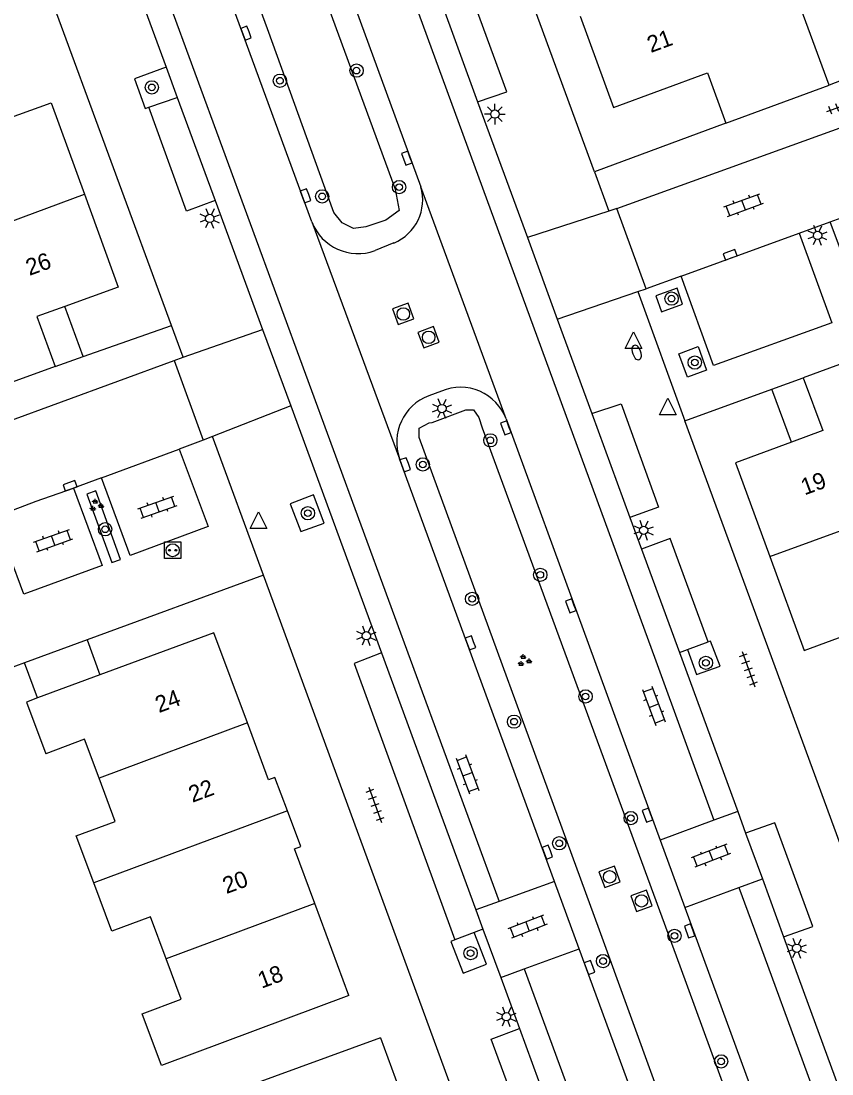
# Model space of a CAD drawing. Extents: x 128000 to 131008, y 398996 to 402500.
# Drawn here: x 128334.1 to 128382.8, y 399087 to 399150.2 of the extents above; entities that cross this region are included whole.
import ezdxf

# ---------------------------------------------------------------- set-up
doc = ezdxf.new("R2010")
doc.units = 0
for name, color, linetype in [('gg-afsc-erfafscheiding', 7, 'Continuous'), ('gg-anno-huisnummerreeks BGT', 7, 'Continuous'), ('gg-bbg-gedigitaliseerde bebouwing', 7, 'Continuous'), ('gg-bbg-hoofdgebouw', 7, 'Continuous'), ('gg-bbg-luifel en loopbrug', 7, 'Continuous'), ('gg-bbg-tussenscheiding', 7, 'Continuous'), ('gg-knt-verharding', 7, 'Continuous'), ('gg-knt-verharding nz', 7, 'Continuous'), ('gt-grn-groengrens NZ', 7, 'Continuous'), ('gt-grn-weggrens', 7, 'Continuous'), ('gt-symb-boom', 7, 'Continuous'), ('gt-symb-brandkraan', 7, 'Continuous'), ('gt-symb-groenvak', 7, 'Continuous'), ('gt-symb-klinker verharding', 7, 'Continuous'), ('gt-symb-kolk', 7, 'Continuous'), ('gt-symb-laadpunt elektrisch vervoer', 7, 'Continuous'), ('gt-symb-lichtmast', 7, 'Continuous'), ('gt-symb-rioolschacht', 7, 'Continuous'), ('gt-symb-tegel verharding', 7, 'Continuous'), ('gt-symb-waterafsluiter', 7, 'Continuous')]:
    doc.layers.add(name, color=color, linetype=linetype)

# ---------------------------------------------------------------- blocks, each defined once
blk = doc.blocks.new('gt0-KOLK')
at = {"layer": 'gt-symb-kolk'}
blk.add_lwpolyline([(0, 0), (0.375, 0), (0.375, 0.4), (-0.375, 0.4), (-0.375, 0), (0, 0)], dxfattribs=at)
blk = doc.blocks.new('gt0-KL1')
at = {"layer": 'gt-symb-klinker verharding'}
for p, q in [((-1.15, 0.3), (1.15, 0.3)), ((-1, -0.3), (-1, 0.3)), ((-0.5, 0.3), (-0.5, 0.45)), ((0, -0.3), (0, 0.3)), ((0.5, 0.3), (0.5, 0.45)), ((1, -0.3), (1, 0.3)), ((-1.15, -0.3), (1.15, -0.3)), ((-0.5, -0.45), (-0.5, -0.3)), ((0.5, -0.45), (0.5, -0.3))]:
    blk.add_line(p, q, dxfattribs=at)
blk = doc.blocks.new('gt0-TEG1')
at = {"layer": 'gt-symb-tegel verharding'}
for p, q in [((-1.125, 0), (1.125, 0)), ((-0.9, -0.25), (-0.9, 0.25)), ((-0.45, -0.25), (-0.45, 0.25)), ((0, -0.25), (0, 0.25)), ((0.45, -0.25), (0.45, 0.25)), ((0.9, -0.25), (0.9, 0.25))]:
    blk.add_line(p, q, dxfattribs=at)
blk = doc.blocks.new('gt0-BOOM')
at = {"layer": 'gt-symb-boom'}
for radius in [0.4, 0.2]:
    blk.add_circle((0, 0), radius, dxfattribs=at)
blk = doc.blocks.new('gt0-RS')
at = {"layer": 'gt-symb-rioolschacht'}
blk.add_lwpolyline([(-0.5, -0.5), (0.5, -0.5), (0.5, 0.5), (-0.5, 0.5)], close=True, dxfattribs=at)
blk.add_circle((0, 0), 0.375, dxfattribs=at)
blk = doc.blocks.new('gt0-LMAST')
at = {"layer": 'gt-symb-lichtmast'}
for p, q in [((-0.182, 0.173), (-0.447, 0.438)), ((-0.005, 0.246), (-0.005, 0.621)), ((0.172, 0.173), (0.437, 0.438)), ((-0.255, -0.004), (-0.63, -0.004)), ((-0.182, -0.181), (-0.447, -0.446)), ((-0.005, -0.254), (-0.005, -0.629)), ((0.437, -0.446), (0.172, -0.181)), ((0.245, -0.004), (0.62, -0.004))]:
    blk.add_line(p, q, dxfattribs=at)
blk.add_circle((-0.005, -0.004), 0.25, dxfattribs=at)
blk = doc.blocks.new('gt0-WAFSL')
at = {"layer": 'gt-symb-waterafsluiter'}
for p, q in [((-0.5, -0.333), (0, 0.667)), ((0, 0.667), (0.5, -0.333)), ((0.5, -0.333), (-0.5, -0.333))]:
    blk.add_line(p, q, dxfattribs=at)
blk = doc.blocks.new('gt0-BR')
at = {"layer": 'gt-symb-brandkraan'}
for centre, radius, start, end in [((-0.244, 0), 0.206, 107.56694, 252.43307), ((0.599, -2.664), 3, 106.89205, 107.56694), ((0, -0.691), 0.938, 73.10799, 106.89205), ((-0.599, -2.664), 3, 72.43309, 73.10799), ((0.244, 0), 0.206, 287.56695, 72.43309), ((0.599, 2.664), 3, 252.43307, 253.10797), ((0, 0.691), 0.938, 253.10797, 286.89206), ((-0.599, 2.664), 3, 286.89206, 287.56695)]:
    blk.add_arc(centre, radius, start, end, dxfattribs=at)
blk = doc.blocks.new('gt0-GRVAK')
at = {"layer": 'gt-symb-groenvak'}
for p, q in [((-0.11, 0.189), (-0.228, 0.24)), ((-0.182, 0.153), (0.088, 0.153)), ((-0.091, 0.211), (-0.156, 0.322)), ((-0.047, 0.214), (-0.047, 0.393)), ((-0.004, 0.211), (0.061, 0.322)), ((0.015, 0.189), (0.133, 0.24)), ((0.262, -0.052), (0.197, 0.059)), ((0.305, -0.049), (0.305, 0.13)), ((0.349, -0.052), (0.414, 0.059)), ((-0.245, -0.228), (-0.363, -0.177)), ((-0.318, -0.264), (-0.047, -0.264)), ((-0.226, -0.206), (-0.291, -0.095)), ((-0.183, -0.203), (-0.183, -0.024)), ((-0.139, -0.206), (-0.074, -0.095)), ((-0.12, -0.228), (-0.002, -0.177)), ((0.243, -0.074), (0.125, -0.023)), ((0.17, -0.11), (0.441, -0.11)), ((0.368, -0.074), (0.486, -0.023))]:
    blk.add_line(p, q, dxfattribs=at)
blk = doc.blocks.new('gt0-LEV')
at = {"layer": 'gt-symb-laadpunt elektrisch vervoer'}
blk.add_lwpolyline([(-0.486, 0.501), (0.486, 0.501), (0.486, -0.499), (-0.486, -0.499)], close=True, dxfattribs=at)
for centre, radius in [((0, 0), 0.393), ((-0.186, 0), 0.0566), ((0.186, 0), 0.0566)]:
    blk.add_circle(centre, radius, dxfattribs=at)

msp = doc.modelspace()

# ---------------------------------------------------------------- linework, layer by layer
at = {"layer": 'gg-afsc-erfafscheiding'}
for p, q in [((128387.99, 399148.45), (128382.63, 399146.39)), ((128334.296, 399111.668), (128322.793, 399107.451))]:
    msp.add_line(p, q, dxfattribs=at)
at = {"layer": 'gg-bbg-gedigitaliseerde bebouwing'}
for points in [[(128338.762, 399104.727), (128337.89, 399107.069), (128335.56, 399106.2)], [(128338.448, 399098.435), (128337.395, 399101.264), (128339.728, 399102.132), (128338.762, 399104.727)], [(128342.8, 399093.881), (128341.862, 399096.4), (128339.53, 399095.531), (128338.448, 399098.435)], [(128353.78, 399091.66), (128342.51, 399087.469), (128341.356, 399090.569), (128343.707, 399091.445), (128342.8, 399093.881)], [(128355.67, 399089.13), (128344.412, 399085.014), (128345.544, 399081.92), (128347.889, 399082.777), (128348.759, 399080.399)]]:
    msp.add_lwpolyline(points, dxfattribs=at)
at = {"layer": 'gg-bbg-hoofdgebouw'}
for p, q in [((128376.42, 399144.11), (128382.63, 399146.39)), ((128390.95, 399132.41), (128381.07, 399128.8)), ((128336.12, 399129.48), (128327.001, 399126.173)), ((128338.817, 399110.942), (128335.064, 399109.555)), ((128353.78, 399091.66), (128351.719, 399097.202)), ((128355.67, 399089.13), (128357.67, 399083.658))]:
    msp.add_line(p, q, dxfattribs=at)
for points in [[(128382.63, 399146.39), (128380.52, 399152.12), (128378.08, 399151.22), (128377.065, 399153.986)], [(128367.664, 399150.54), (128369.68, 399145.05), (128375.32, 399147.12), (128376.42, 399144.11)], [(128332.702, 399144.175), (128335.88, 399145.33), (128337.881, 399139.829)], [(128337.881, 399139.829), (128339.91, 399134.25), (128336.708, 399133.089)], [(128336.708, 399133.089), (128335.03, 399132.48), (128336.12, 399129.48)], [(128381.07, 399128.8), (128382.24, 399125.63), (128380.366, 399124.932)], [(128380.366, 399124.932), (128377, 399123.68), (128379.064, 399118.047)], [(128379.064, 399118.047), (128381.13, 399112.41), (128384.493, 399113.649)], [(128347.68, 399108.048), (128345.66, 399113.47), (128338.817, 399110.942)], [(128335.064, 399109.555), (128334.4, 399109.31), (128335.56, 399106.2)], [(128350.08, 399102.766), (128349.33, 399104.78), (128348.95, 399104.64), (128347.68, 399108.048)], [(128351.719, 399097.202), (128350.5, 399100.48), (128350.88, 399100.62), (128350.08, 399102.766)]]:
    msp.add_lwpolyline(points, dxfattribs=at)
at = {"layer": 'gg-bbg-luifel en loopbrug'}
for p, q in [((128337.818, 399130.077), (128336.708, 399133.089)), ((128336.12, 399129.48), (128337.818, 399130.077)), ((128379.182, 399128.113), (128381.07, 399128.8)), ((128380.366, 399124.932), (128379.182, 399128.113)), ((128338.052, 399113.045), (128334.296, 399111.668)), ((128338.052, 399113.045), (128338.817, 399110.942)), ((128335.064, 399109.555), (128334.296, 399111.668))]:
    msp.add_line(p, q, dxfattribs=at)
at = {"layer": 'gg-bbg-tussenscheiding'}
for p, q in [((128329.843, 399136.835), (128337.881, 399139.829)), ((128379.064, 399118.047), (128390.334, 399122.193)), ((128347.68, 399108.048), (128338.762, 399104.727)), ((128350.08, 399102.766), (128338.448, 399098.435)), ((128351.719, 399097.202), (128342.8, 399093.881))]:
    msp.add_line(p, q, dxfattribs=at)
at = {"layer": 'gg-knt-verharding'}
for p, q in [((128368.53, 399141.17), (128349.82, 399192.151)), ((128343.12, 399131.94), (128324.56, 399182.36)), ((128349.985, 399162.408), (128358.097, 399140.276)), ((128351.554, 399138.165), (128343.596, 399159.823)), ((128339.739, 399155.796), (128342.797, 399147.471)), ((128342.797, 399147.471), (128343.466, 399145.649)), ((128369.87, 399138.98), (128392.622, 399147.204)), ((128341.765, 399145.061), (128343.466, 399145.649)), ((128361.506, 399145.394), (128364.496, 399137.232)), ((128376.42, 399144.11), (128368.53, 399141.17)), ((128345.743, 399139.452), (128348.588, 399131.706)), ((128371.63, 399134.15), (128369.87, 399138.98)), ((128380.83, 399137.492), (128382.694, 399138.17)), ((128364.496, 399137.232), (128366.293, 399132.326)), ((128356.48, 399136.9), (128355.349, 399136.45)), ((128373.734, 399134.914), (128371.63, 399134.15)), ((128366.293, 399132.326), (128368.373, 399126.648)), ((128337.818, 399130.077), (128343.12, 399131.94)), ((128348.588, 399131.706), (128350.277, 399127.108)), ((128343.272, 399129.838), (128345.027, 399125.049)), ((128359.34, 399128.001), (128358.57, 399127.72)), ((128373.95, 399126.21), (128379.182, 399128.113)), ((128350.277, 399127.108), (128355.727, 399112.271)), ((128363.22, 399126.33), (128372.471, 399101.015)), ((128405.733, 399039.553), (128373.95, 399126.21)), ((128345.027, 399125.049), (128343.575, 399124.508)), ((128366.131, 399098.53), (128356.823, 399123.932)), ((128338.912, 399122.783), (128337.221, 399122.164)), ((128370.661, 399120.4), (128371.356, 399118.503)), ((128348.65, 399116.93), (128338.052, 399113.045)), ((128367.65, 399065.05), (128348.65, 399116.93)), ((128374.11, 399112.468), (128375.357, 399112.917)), ((128373.63, 399112.295), (128374.11, 399112.468)), ((128373.63, 399112.295), (128377.134, 399102.73)), ((128377.134, 399102.73), (128375.692, 399102.2)), ((128377.134, 399102.73), (128377.609, 399101.433)), ((128375.692, 399102.2), (128372.471, 399101.015)), ((128372.471, 399101.015), (128373.955, 399096.954)), ((128377.195, 399098.162), (128378.613, 399098.691)), ((128366.131, 399098.53), (128362.81, 399097.328)), ((128367.615, 399094.48), (128366.131, 399098.53)), ((128373.955, 399096.954), (128377.195, 399098.162)), ((128362.81, 399097.328), (128361.402, 399096.819)), ((128373.955, 399096.954), (128382.45, 399073.709)), ((128361.298, 399095.459), (128360.143, 399095.009)), ((128361.826, 399095.665), (128361.298, 399095.459)), ((128361.826, 399095.665), (128362.894, 399092.756)), ((128379.89, 399095.204), (128383.914, 399084.219)), ((128364.3, 399093.269), (128367.615, 399094.48)), ((128376.08, 399071.38), (128367.615, 399094.48)), ((128362.894, 399092.756), (128364.3, 399093.269)), ((128362.894, 399092.756), (128364.021, 399089.688))]:
    msp.add_line(p, q, dxfattribs=at)
for points in [[(128361.506, 399145.394), (128363.263, 399145.978), (128359.248, 399156.921)], [(128342.797, 399147.471), (128340.894, 399146.772), (128341.527, 399144.979), (128341.765, 399145.061)], [(128345.743, 399139.452), (128344.026, 399138.818), (128341.765, 399145.061)], [(128389.754, 399140.734), (128391.714, 399135.405), (128384.681, 399132.818), (128382.694, 399138.17)], [(128380.83, 399137.492), (128382.783, 399132.104), (128375.685, 399129.535), (128373.734, 399134.914)], [(128372.547, 399132.77), (128373.82, 399133.219), (128373.493, 399134.191), (128372.222, 399133.729), (128372.547, 399132.77)], [(128373.595, 399130.246), (128374.747, 399130.688), (128375.263, 399129.264), (128374.118, 399128.838), (128373.595, 399130.246)], [(128295.703, 399112.316), (128333.127, 399126.116), (128343.272, 399129.838)], [(128368.373, 399126.648), (128370.122, 399127.234), (128372.376, 399121.014), (128370.661, 399120.4)], [(128343.575, 399124.508), (128345.325, 399119.858), (128340.633, 399118.126), (128338.912, 399122.783)], [(128337.221, 399122.164), (128338.957, 399117.507), (128334.255, 399115.794), (128332.512, 399120.442)], [(128339.542, 399117.698), (128340.058, 399117.884), (128338.577, 399122), (128338.039, 399121.803), (128339.542, 399117.698)], [(128350.893, 399119.563), (128352.298, 399120.063), (128351.655, 399121.759), (128350.252, 399121.227), (128350.893, 399119.563)], [(128375.357, 399112.917), (128373.072, 399119.145), (128371.356, 399118.503)], [(128374.11, 399112.468), (128374.655, 399110.955), (128376.068, 399111.472), (128375.507, 399112.971), (128375.357, 399112.917)], [(128355.727, 399112.271), (128354.087, 399111.63), (128360.143, 399095.009)], [(128379.89, 399095.204), (128381.644, 399095.816), (128379.364, 399102.055), (128377.609, 399101.433)], [(128360.143, 399095.009), (128359.9, 399094.914), (128360.641, 399093.013), (128362.039, 399093.558), (128361.298, 399095.459)], [(128366.338, 399078.12), (128362.33, 399089.049), (128364.021, 399089.688)]]:
    msp.add_lwpolyline(points, dxfattribs=at)
for centre, radius, start, end in [((128355.394, 399139.495), 2.813, 292.69937, 16.11466), ((128354.318, 399139.225), 2.961, 200.98712, 290.37547), ((128359.634, 399124.933), 2.984, 110.8884, 199.59393), ((128360.473, 399125.293), 2.936, 20.69272, 112.70708)]:
    msp.add_arc(centre, radius, start, end, dxfattribs=at)
at = {"layer": 'gg-knt-verharding nz'}
for p, q in [((128340.294, 399158.628), (128362.81, 399097.328)), ((128357.518, 399156.284), (128361.506, 399145.394)), ((128343.466, 399145.649), (128345.743, 399139.452)), ((128382.694, 399138.17), (128389.754, 399140.734)), ((128373.734, 399134.914), (128380.83, 399137.492)), ((128368.373, 399126.648), (128370.661, 399120.4)), ((128338.912, 399122.783), (128343.575, 399124.508)), ((128371.356, 399118.503), (128373.63, 399112.295)), ((128355.727, 399112.271), (128361.402, 399096.819)), ((128377.609, 399101.433), (128378.613, 399098.691)), ((128378.613, 399098.691), (128379.89, 399095.204)), ((128361.402, 399096.819), (128361.826, 399095.665)), ((128364.021, 399089.688), (128368.036, 399078.759))]:
    msp.add_line(p, q, dxfattribs=at)
for points in [[(128353.225, 399163.609), (128356.11, 399155.767), (128372.221, 399111.782), (128375.692, 399102.2)], [(128332.512, 399120.442), (128334.988, 399121.391), (128337.221, 399122.164)], [(128377.195, 399098.162), (128378.482, 399094.686), (128388.815, 399066.479), (128396.32, 399045.94)], [(128364.3, 399093.269), (128378.665, 399054.148), (128383.385, 399041.232)]]:
    msp.add_lwpolyline(points, dxfattribs=at)
at = {"layer": 'gt-grn-groengrens NZ'}
for points in [[(128336.108, 399184.622), (128336.155, 399184.935), (128336.312, 399185.359), (128336.751, 399185.923), (128337.111, 399186.127), (128338.256, 399186.566), (128338.726, 399186.613), (128339.039, 399186.425), (128339.494, 399186.284), (128339.902, 399185.564), (128356.552, 399140.132), (128356.797, 399138.847), (128355.998, 399138.277), (128354.801, 399137.878), (128354.06, 399137.764), (128353.375, 399138.106), (128352.862, 399138.733), (128348.878, 399149.771), (128336.237, 399184.198), (128336.108, 399184.622)], [(128358.003, 399125.21), (128358.003, 399125.77), (128358.595, 399126.082), (128358.774, 399126.105), (128360.808, 399126.868), (128361.266, 399126.868), (128361.571, 399126.41), (128361.774, 399125.799), (128373.658, 399093.454), (128381.033, 399073.256), (128381.288, 399072.34), (128380.27, 399071.678), (128379.202, 399071.119), (128378.49, 399071.119), (128377.88, 399071.373), (128377.422, 399071.933), (128368.837, 399095.599), (128358.003, 399125.21)]]:
    msp.add_lwpolyline(points, dxfattribs=at)
at = {"layer": 'gt-grn-weggrens'}
for p, q in [((128368.53, 399141.17), (128369.381, 399138.821)), ((128363.22, 399126.33), (128358.097, 399140.276)), ((128369.381, 399138.821), (128364.496, 399137.232)), ((128369.87, 399138.98), (128369.381, 399138.821)), ((128351.554, 399138.165), (128356.823, 399123.932)), ((128371.135, 399133.981), (128371.63, 399134.15)), ((128366.293, 399132.326), (128371.135, 399133.981)), ((128371.135, 399133.981), (128373.95, 399126.21)), ((128343.823, 399130.032), (128343.12, 399131.94)), ((128343.823, 399130.032), (128348.588, 399131.706)), ((128343.272, 399129.838), (128343.823, 399130.032)), ((128350.277, 399127.108), (128345.579, 399125.265)), ((128345.579, 399125.265), (128345.027, 399125.049)), ((128348.65, 399116.93), (128345.579, 399125.265))]:
    msp.add_line(p, q, dxfattribs=at)

# ---------------------------------------------------------------- block references
at = {"layer": 'gt-symb-boom'}
for p, rotation in [((128354.236, 399147.26), -69.93365037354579), ((128349.634, 399146.656), -69.93365037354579), ((128352.17, 399139.704), -69.93365037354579), ((128365.274, 399116.955), -69.62510008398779), ((128361.175, 399115.512), -69.87983420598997), ((128367.99, 399109.643), -69.62510008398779), ((128363.695, 399108.128), -69.62510008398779), ((128370.707, 399102.331), -69.62510008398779), ((128366.412, 399100.816), -69.62510008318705), ((128373.336, 399095.254), -69.62510008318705), ((128369.041, 399093.739), -69.62510008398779), ((128376.139, 399087.708), -69.62510008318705)]:
    msp.add_blockref('gt0-BOOM', p, dxfattribs=dict(at, rotation=rotation))
for p in [(128341.935, 399146.255), (128356.789, 399140.261), (128373.157, 399133.555), (128374.554, 399129.712), (128362.271, 399125.039), (128358.215, 399123.591), (128351.312, 399120.656), (128339.13, 399119.69), (128375.224, 399111.664), (128361.088, 399094.212)]:
    msp.add_blockref('gt0-BOOM', p, dxfattribs=at)
at = {"layer": 'gt-symb-brandkraan', "rotation": -69.87983420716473}
msp.add_blockref('gt0-BR', (128371.058, 399130.32), dxfattribs=at)
at = {"layer": 'gt-symb-groenvak'}
for p in [(128338.584, 399121.128), (128364.299, 399111.793)]:
    msp.add_blockref('gt0-GRVAK', p, dxfattribs=at)
at = {"layer": 'gt-symb-klinker verharding'}
for p, rotation in [((128377.49, 399139.176), 19.885165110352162), ((128342.279, 399121.02), 19.44956876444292), ((128336.003, 399119.012), 19.44956876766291), ((128372.091, 399109.088), -69.87983420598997), ((128360.9, 399104.967), -69.8798342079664), ((128375.522, 399100.07), -158.9007877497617), ((128364.505, 399095.813), -158.9007877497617)]:
    msp.add_blockref('gt0-KL1', p, dxfattribs=dict(at, rotation=rotation))
at = {"layer": 'gt-symb-kolk'}
for p, rotation in [((128347.779, 399149.589), 110.17394494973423), ((128357.439, 399142.066), 110.1739449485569), ((128351.361, 399139.809), 110.1739449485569), ((128376.741, 399136.005), 19.939047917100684), ((128363.39, 399125.859), 110.1739449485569), ((128357.345, 399123.644), 110.1739449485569), ((128337.088, 399122.117), 19.08724450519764), ((128367.291, 399115.16), 110.17394494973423), ((128361.269, 399112.936), 110.1739449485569), ((128371.895, 399102.582), 110.1739449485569), ((128365.884, 399100.356), 110.1739449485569), ((128374.431, 399095.616), 110.1739449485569), ((128368.421, 399093.414), 110.1739449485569)]:
    msp.add_blockref('gt0-KOLK', p, dxfattribs=dict(at, rotation=rotation))
at = {"layer": 'gt-symb-laadpunt elektrisch vervoer'}
msp.add_blockref('gt0-LEV', (128343.187, 399118.429), dxfattribs=at)
at = {"layer": 'gt-symb-lichtmast'}
msp.add_blockref('gt0-LMAST', (128362.547, 399144.65), dxfattribs=at)
for p, rotation in [((128345.411, 399138.38), 110.1739449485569), ((128381.931, 399137.361), 19.93904791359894), ((128359.358, 399126.943), -159.879834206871), ((128371.477, 399119.624), -159.87983420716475), ((128354.819, 399113.292), 110.1739449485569), ((128380.678, 399094.503), -159.87983420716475), ((128363.23, 399090.391), 110.17394494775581)]:
    msp.add_blockref('gt0-LMAST', p, dxfattribs=dict(at, rotation=rotation))
at = {"layer": 'gt-symb-rioolschacht'}
for p, rotation in [((128357.041, 399132.636), -69.87983420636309), ((128358.565, 399131.232), -69.87983420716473), ((128369.439, 399098.799), -69.87983420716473), ((128371.35, 399097.354), -69.87983420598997)]:
    msp.add_blockref('gt0-RS', p, dxfattribs=dict(at, rotation=rotation))
at = {"layer": 'gt-symb-tegel verharding'}
for p, rotation in [((128383.541, 399145.183), 19.88516511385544), ((128377.778, 399111.283), -69.87983420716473), ((128355.349, 399103.13), -69.87983420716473)]:
    msp.add_blockref('gt0-TEG1', p, dxfattribs=dict(at, rotation=rotation))
at = {"layer": 'gt-symb-waterafsluiter'}
for p in [(128370.865, 399130.892), (128372.94, 399126.914), (128348.335, 399120.071)]:
    msp.add_blockref('gt0-WAFSL', p, dxfattribs=at)

# ---------------------------------------------------------------- texts
at = {"layer": 'gg-anno-huisnummerreeks BGT'}
for s, rotation, p in [('21', 20.2, (128371.913, 399148.319)), ('26', 19.9, (128334.583, 399134.921)), ('19', 20.1, (128381.148, 399121.726)), ('24', 20.4, (128342.362, 399108.64)), ('22', 20.4, (128344.371, 399103.248)), ('20', 20.4, (128346.415, 399097.762)), ('18', 20.4, (128348.53, 399092.075))]:
    msp.add_text(s, height=1, rotation=rotation, dxfattribs=at).set_placement(p)

doc.saveas('drawing.dxf')
